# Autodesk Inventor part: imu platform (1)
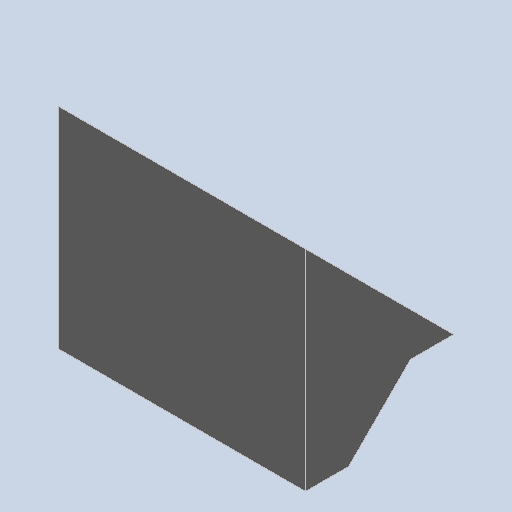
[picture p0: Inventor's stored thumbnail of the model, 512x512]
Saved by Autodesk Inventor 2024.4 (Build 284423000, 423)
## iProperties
Created: 2025-04
Part Number: imu platform (1)
Material: Generic
Document SubType Name: Modeling
Designer: AdminForWorker
Density: 1 g/cm^3
Appearance: Default
Title: imu platform (1) v1
Author: AdminForWorker
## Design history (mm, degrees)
feature "Body6"
body "Solid1"
